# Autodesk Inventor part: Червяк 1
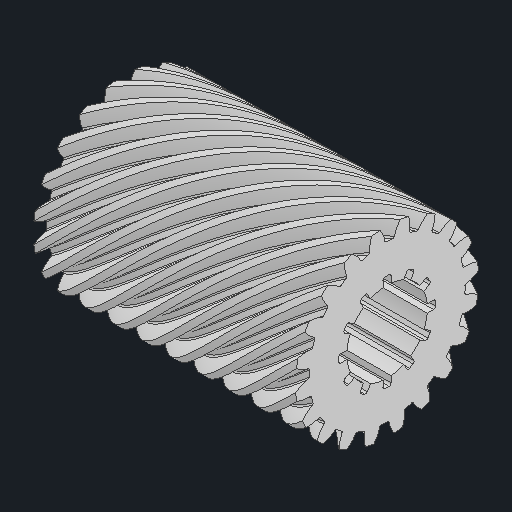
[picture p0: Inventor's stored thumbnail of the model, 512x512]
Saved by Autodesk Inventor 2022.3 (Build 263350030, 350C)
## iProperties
Created: 2020-09
Part Number: Червяк 1
Material: Типовые
Document SubType Name: Modeling
Designer: Карташов
Density: 1 g/cm^3
Appearance: По умолчанию
Title: D:\мои документы\Ирина\_WorldSkills\2020_09 ФНЧ\Module A\GIVEN\Червяк 1.stp
Author: Дом
Sending System: Autodesk Inventor 2021
Preprocessor: ST-DEVELOPER v18.1
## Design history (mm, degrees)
feature "Твердое тело2"
node "Твердое тело1"
